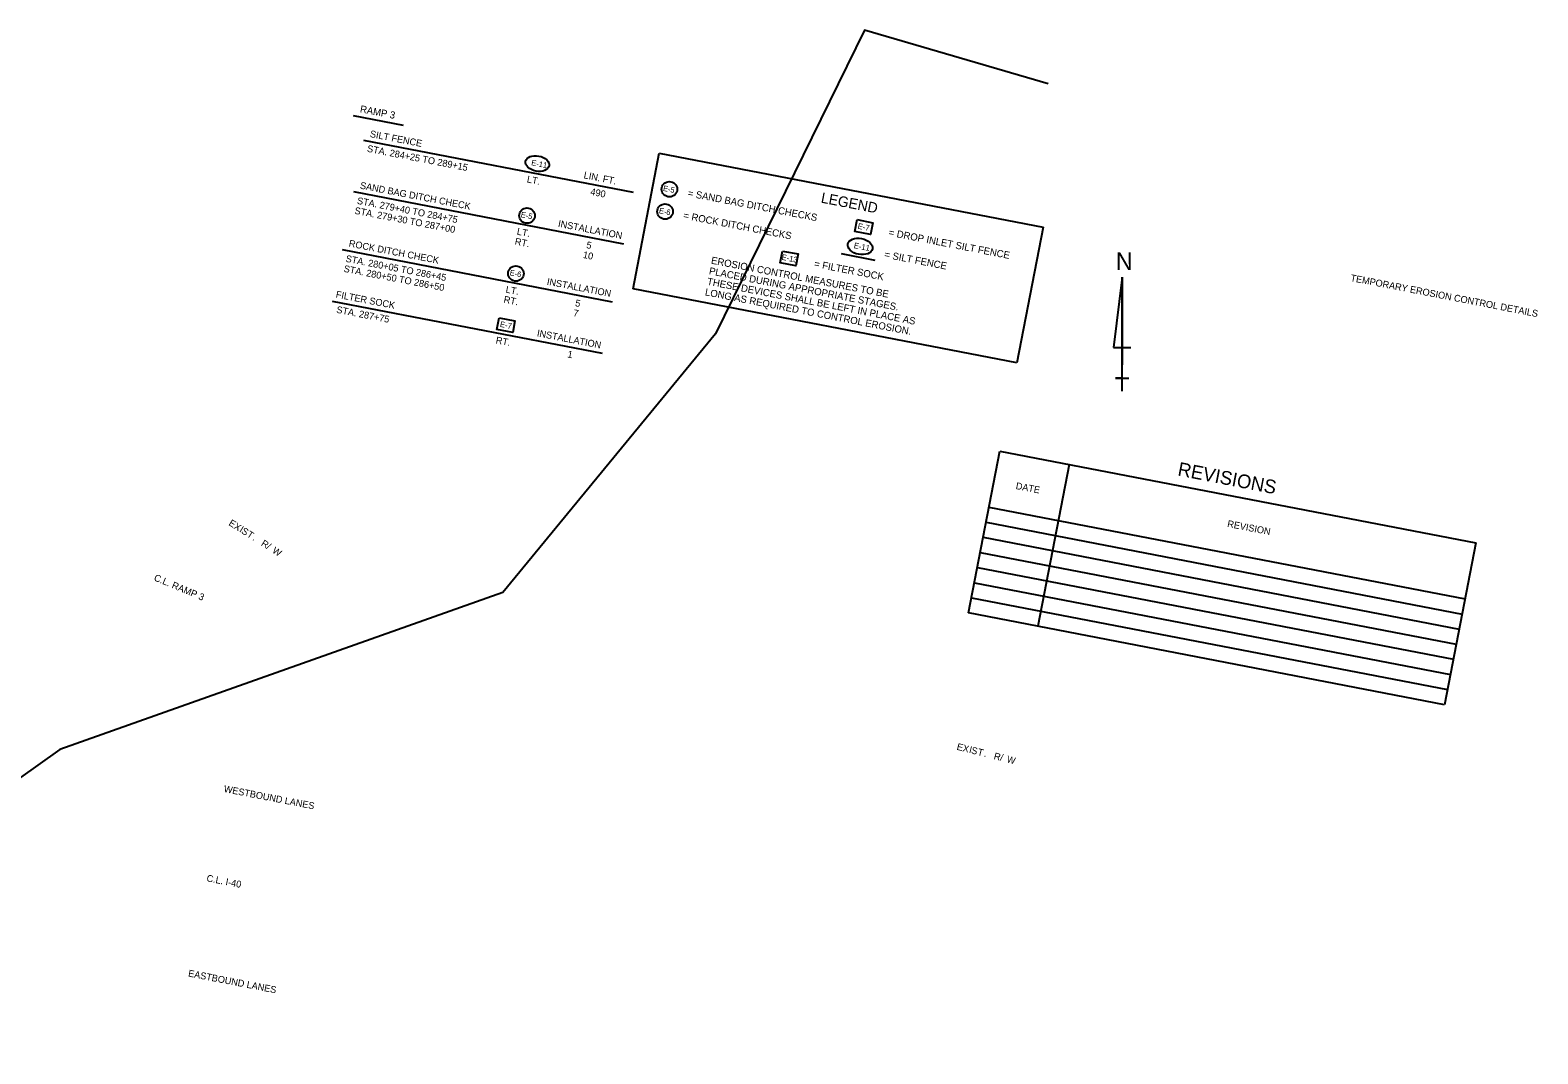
# Model space of a CAD drawing. Extents: x 609582 to 612199, y 418411 to 420210.
# Drawn here: x 610877 to 612199, y 419313 to 420210 of the extents above; entities that cross this region are included whole.
import ezdxf

# ---------------------------------------------------------------- set-up
doc = ezdxf.new("R2010")
doc.units = 0
for name, color, linetype in [('1', 7, 'Continuous'), ('44', 7, 'Continuous'), ('Default', 7, 'Continuous'), ('G-ANNO-TEXT', 7, 'Continuous'), ('Level 1', 7, 'Continuous'), ('Level 44', 7, 'Continuous'), ('R_Draft', 7, 'Continuous'), ('X_ARROWS_LEGEND', 7, 'Continuous')]:
    doc.layers.add(name, color=color, linetype=linetype)

msp = doc.modelspace()

# ---------------------------------------------------------------- linework, layer by layer
at = {"layer": '1'}
msp.add_ellipse((611321.8, 420093.3), major_axis=(10.3, -2), ratio=0.638788, dxfattribs=at)
at = {"layer": 'G-ANNO-TEXT'}
for p, q in [((611160.5, 420135.5), (611204.3, 420127)), ((611169.3, 420113.8), (611405.9, 420068.1)), ((611160.6, 420068.7), (611397.2, 420023)), ((611150.7, 420017.8), (611387.4, 419972.1)), ((611142, 419972.6), (611378.7, 419927))]:
    msp.add_line(p, q, dxfattribs=at)
at = {"layer": 'Level 44'}
msp.add_lwpolyline([(611588.1, 420014.4), (611617.7, 420008.7)], dxfattribs=at)
at = {"layer": 'R_Draft'}
for points in [[(611769.6, 420163.3), (611608.6, 420210.3), (611478, 419944)], [(611478, 419944), (611291.7, 419717.1), (610903.4, 419579.6)], [(610903.4, 419579.6), (610554.2, 419331.2), (609660.1, 418415.1)]]:
    msp.add_lwpolyline(points, dxfattribs=at)
at = {"layer": 'X_ARROWS_LEGEND'}
for p, q in [((611405.7, 419983.5), (611428.6, 420102.4)), ((611428.6, 420102.4), (611765.1, 420037.4)), ((611765.1, 420037.4), (611742.1, 419918.6)), ((611834.4, 419993.6), (611826.7, 419932)), ((611834.4, 419893.6), (611834.4, 419993.6)), ((611834.4, 419993.6), (611834.4, 419916.7)), ((611742.1, 419918.6), (611405.7, 419983.5)), ((611826.7, 419932), (611842.1, 419932)), ((611834.4, 419893.6), (611834.4, 419916.7)), ((611834.4, 419905.1), (611828.6, 419905.1)), ((611828.6, 419905.1), (611840.2, 419905.1)), ((611834.4, 419893.6), (611834.4, 419905.1)), ((611699.8, 419699.3), (611727.2, 419841.2)), ((611727.2, 419841.2), (612144.5, 419760.7)), ((611787.9, 419829.5), (611760.5, 419687.6)), ((611717.7, 419792.1), (612135, 419711.6)), ((611715.2, 419778.9), (612132.4, 419698.3)), ((611712.6, 419765.6), (612129.9, 419685.1)), ((611710, 419752.4), (612127.3, 419671.8)), ((611710, 419752.4), (612127.3, 419671.8)), ((612144.5, 419760.7), (612117.1, 419618.8)), ((611707.5, 419739.1), (612124.8, 419658.6)), ((611704.9, 419725.8), (612122.2, 419645.3)), ((611702.4, 419712.6), (612119.7, 419632)), ((612117.1, 419618.8), (611699.8, 419699.3))]:
    msp.add_line(p, q, dxfattribs=at)
for points in [[(611602, 420044.1), (611615.8, 420041.4), (611613.8, 420031.1), (611600, 420033.8)], [(611536.7, 420016.6), (611550.4, 420014), (611548.5, 420003.7), (611534.7, 420006.3)], [(611288.4, 419958.1), (611302.2, 419955.4), (611300.2, 419945.1), (611286.4, 419947.8)]]:
    msp.add_lwpolyline(points, close=True, dxfattribs=at)
for centre, major_axis, ratio in [((611437.6, 420070.8), (-6.76, 1.31), 0.97521), ((611312.8, 420047.6), (-6.76, 1.31), 0.97521), ((611433.8, 420051.2), (-6.76, 1.31), 0.97521), ((611604.7, 420020.6), (10.8, -2.1), 0.638788), ((611303, 419996.8), (-6.76, 1.31), 0.97521)]:
    msp.add_ellipse(centre, major_axis=major_axis, ratio=ratio, dxfattribs=at)

# ---------------------------------------------------------------- texts
at = {"layer": '1'}
msp.add_text('E-11', height=4.8, rotation=349.0745, dxfattribs=at).set_placement((611316.2, 420091.9))
at = {"layer": '44'}
msp.add_text('SILT FENCE      ', height=6, rotation=349.0745, dxfattribs=at).set_placement((611174.7, 420116.6))
at = {"layer": 'Default'}
msp.add_text('C.L. RAMP 3', height=6, rotation=337.1402, dxfattribs=at).set_placement((610985.2, 419728))
at = {"layer": 'G-ANNO-TEXT'}
for s, height, p in [('RAMP 3', 6.25, (611166, 420138.3)), ('SILT FENCE', 6, (611174.7, 420116.6)), ('STA. 284+25 TO 289+15', 6, (611172.2, 420103.7)), ('LT. ', 6, (611312.3, 420076.8)), ('LIN. FT.', 6, (611362.1, 420080.4)), ('SAND BAG DITCH CHECK', 6, (611166, 420071.4)), ('490', 6, (611367.9, 420065.9)), ('STA. 279+30 TO 287+00', 6, (611161.2, 420049.3)), ('STA. 279+40 TO 284+75', 6, (611163.4, 420058)), ('INSTALLATION ', 6, (611339.6, 420037.9)), ('ROCK DITCH CHECK', 6, (611156.2, 420020.6)), ('RT. ', 6, (611301.7, 420022.3)), ('LT. ', 6, (611303.5, 420031)), ('STA. 280+05 TO 286+45', 6, (611153.4, 420007.2)), ('10', 6, (611361.4, 420010.6)), ('5', 6, (611364.4, 420019.2)), ('STA. 280+50 TO 286+50', 6, (611151.7, 419998.4)), ('LT. ', 6, (611293.7, 419980.2)), ('INSTALLATION ', 6, (611329.8, 419987.1)), ('TEMPORARY EROSION CONTROL DETAILS', 6, (612034.2, 419990.3)), ('FILTER SOCK', 6, (611144.8, 419975.9)), ('RT. ', 6, (611291.9, 419971.4)), ('5', 6, (611354.6, 419968.3)), ('STA. 287+75', 6, (611145.3, 419962.5)), ('7', 6, (611352.9, 419959.6)), ('INSTALLATION ', 6, (611321.1, 419941.9)), ('RT. ', 6, (611285, 419935.7)), ('1', 6, (611347.8, 419923.4))]:
    msp.add_text(s, height=height, rotation=349.0745, dxfattribs=at).set_placement(p)
at = {"layer": 'Level 1'}
for s, p in [('= DROP INLET SILT FENCE', (611629.3, 420030.1)), ('= SILT FENCE', (611625.6, 420010.8)), ('= FILTER SOCK', (611564, 420002.6))]:
    msp.add_text(s, height=6.25, rotation=349.0745, dxfattribs=at).set_placement(p)
at = {"layer": 'R_Draft'}
for s, rotation, p in [('E', 327.7725, (611050.7, 419776.6)), ('X', 327.7725, (611055.3, 419773.7)), ('I', 327.7725, (611060.1, 419770.7)), ('S', 327.7725, (611061.8, 419769.6)), ('T', 327.7725, (611066.6, 419766.6)), ('.', 327.7725, (611071.6, 419763.4)), ('R', 327.7725, (611079.1, 419758.7)), ('/', 327.7725, (611083.9, 419755.7)), ('W', 327.7725, (611088.9, 419752.5)), ('E', 345.8227, (611689, 419579.4)), ('X', 345.8227, (611694.2, 419578.1)), ('I', 345.8227, (611699.8, 419576.7)), ('S', 345.8227, (611701.7, 419576.2)), ('T', 345.8227, (611707.2, 419574.8)), ('R', 345.8227, (611721.5, 419571.2)), ('.', 345.8227, (611712.9, 419573.4)), ('/', 345.8227, (611727, 419569.8)), ('W', 345.8227, (611732.7, 419568.4)), ('WESTBOUND LANES', 349.0745, (611046.6, 419542.3)), ('C.L. I-40', 349.0745, (611031.5, 419464)), ('EASTBOUND LANES', 349.0745, (611015.4, 419380.6))]:
    msp.add_text(s, height=6, rotation=rotation, dxfattribs=at).set_placement(p)
at = {"layer": 'X_ARROWS_LEGEND'}
for s, height, rotation, p in [('E-5', 4.88, 349.0745, (611431.7, 420069.4)), ('= SAND BAG DITCH CHECKS', 6.25, 349.0745, (611453.2, 420064.6)), ('LEGEND', 9.14, 349.0745, (611569.9, 420059.1)), ('E-6', 4.88, 349.0745, (611428.1, 420049.8)), ('E-5', 4.88, 349.0745, (611307, 420046.3)), ('= ROCK DITCH CHECKS', 6.25, 349.0745, (611449.4, 420045)), ('E-7', 5, 348.6922, (611602.3, 420036.2)), ('E-13', 5, 348.6922, (611535.6, 420009)), ('E-11', 5, 349.0745, (611598.9, 420019.2)), ('N', 15.4, 360, (611828.8, 420000)), ('E-6', 4.88, 349.0745, (611297.3, 419995.4)), ('PLACED DURING APPROPRIATE STAGES. ', 6.25, 349.0745, (611471.9, 419996.3)), ('EROSION CONTROL MEASURES TO BE', 6.25, 349.0745, (611473.7, 420005.6)), ('THESE DEVICES SHALL BE LEFT IN PLACE AS ', 6.25, 349.0745, (611470.2, 419987.1)), ('LONG AS REQUIRED TO CONTROL EROSION.', 6.25, 349.0745, (611468.4, 419977.8)), ('E-7', 5, 348.6922, (611288.7, 419950.2)), ('REVISIONS', 12, 349.0745, (611882.5, 419819.9)), ('DATE', 6, 349.0745, (611740.8, 419808)), ('REVISION', 6, 349.0745, (611926.2, 419774.8))]:
    msp.add_text(s, height=height, rotation=rotation, dxfattribs=at).set_placement(p)

doc.saveas('drawing.dxf')
